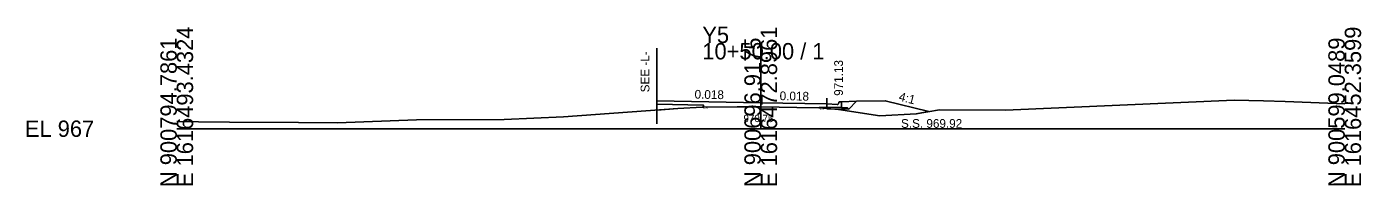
# Model space of a CAD drawing. Extents: x -26 to 1403, y -10 to 4517.
# Drawn here: x -25.7 to 202.8, y 490.3 to 517.5 of the extents above; entities that cross this region are included whole.
import ezdxf

# ---------------------------------------------------------------- set-up
doc = ezdxf.new("R2010")
doc.units = 0
for name, color, linetype in [('Exist Cross Section Cell', 7, 'Continuous'), ('Exist XS Center Line Elevation Label', 7, 'Continuous'), ('Exist XS Ground Line', 7, 'Continuous'), ('Prop XS Dump Level', 7, 'Continuous'), ('Prop XS Earthwork Shape', 7, 'Continuous'), ('Prop XS EOT Tick Mark', 7, 'Continuous'), ('Prop XS Finish Grade', 7, 'Continuous'), ('Prop XS Finish Grade CurbGutter', 7, 'Continuous'), ('Prop XS Finish Grade Earthwork', 7, 'Continuous'), ('Prop XS Finish Grade Pavement', 7, 'Continuous'), ('Prop XS Hydro Elevations', 7, 'Continuous'), ('Prop XS Pvmt Edge Slope', 7, 'Continuous'), ('Prop XS SE Text', 7, 'Continuous'), ('Prop XS Side Slope Text', 7, 'Continuous'), ('Prop XS SS Elevation Text', 7, 'Continuous'), ('Prop XS Subgrade CurbGutter', 7, 'Continuous'), ('Prop XS Subgrade Earthwork', 7, 'Continuous')]:
    doc.layers.add(name, color=color, linetype=linetype)

msp = doc.modelspace()

# ---------------------------------------------------------------- linework, layer by layer
at = {"layer": 'Exist Cross Section Cell'}
for p, q in [((100, 500), (100, 514.67)), ((0, 500), (100, 500)), ((100, 500), (200, 500))]:
    msp.add_line(p, q, dxfattribs=at)
at = {"layer": 'Exist XS Ground Line'}
for p, q in [((66.23, 502.01), (85.83, 503.47)), ((85.83, 503.47), (89.98, 503.69)), ((89.98, 503.69), (95.97, 503.75)), ((95.97, 503.75), (100.12, 503.75)), ((100.12, 503.75), (106.18, 503.64)), ((106.18, 503.64), (109.96, 503.59)), ((109.96, 503.59), (110.73, 503.53)), ((110.73, 503.53), (113.33, 503.27)), ((113.33, 503.27), (120.41, 502.22)), ((126.63, 502.53), (130.62, 503.25)), ((130.62, 503.25), (141.91, 503.15)), ((141.91, 503.15), (181.09, 504.89)), ((181.09, 504.89), (186.07, 504.77)), ((186.07, 504.77), (189.8, 504.68)), ((189.8, 504.68), (200, 504.26)), ((0, 501.21), (3.71, 501.2)), ((3.71, 501.2), (9.02, 501.11)), ((9.02, 501.11), (20.85, 501.08)), ((20.85, 501.08), (27.54, 501.02)), ((27.54, 501.02), (41.06, 501.51)), ((41.06, 501.51), (56.08, 501.6)), ((56.08, 501.6), (66.23, 502.01)), ((120.41, 502.22), (126.63, 502.53))]:
    msp.add_line(p, q, dxfattribs=at)
at = {"layer": 'Prop XS Dump Level'}
for p, q in [((82.19, 504.77), (100, 504.45)), ((100, 504.45), (111.33, 504.25))]:
    msp.add_line(p, q, dxfattribs=at)
at = {"layer": 'Prop XS Earthwork Shape'}
for points in [[(82.19, 503.2), (85.83, 503.47), (89.98, 503.69), (90.19, 503.69), (90.19, 504.04), (82.19, 504.19)], [(110.12, 503.58), (110.73, 503.53), (111.33, 503.47), (111.33, 503.66), (110.12, 503.68)], [(111.33, 503.47), (111.98, 503.4), (111.33, 503.42)], [(111.98, 503.4), (113.33, 503.27), (120.41, 502.22), (126.63, 502.53), (128.8, 502.92), (121.33, 504.79), (116.42, 504.69), (115.08, 503.35)]]:
    msp.add_lwpolyline(points, close=True, dxfattribs=at)
at = {"layer": 'Prop XS EOT Tick Mark'}
for p, q in [((82.19, 500.85), (82.19, 513.78)), ((111.33, 504.25), (111.33, 505.25))]:
    msp.add_line(p, q, dxfattribs=at)
at = {"layer": 'Prop XS Finish Grade'}
msp.add_line((113.83, 504.63), (116.42, 504.69), dxfattribs=at)
at = {"layer": 'Prop XS Finish Grade CurbGutter'}
for p, q in [((111.33, 504.25), (113.08, 504.15)), ((113.08, 504.15), (113.2, 504.17)), ((113.2, 504.17), (113.3, 504.26)), ((113.3, 504.26), (113.36, 504.51)), ((113.36, 504.51), (113.45, 504.6)), ((113.58, 504.63), (113.45, 504.6)), ((113.83, 504.63), (113.58, 504.63))]:
    msp.add_line(p, q, dxfattribs=at)
at = {"layer": 'Prop XS Finish Grade Earthwork'}
for p, q in [((116.42, 504.69), (121.33, 504.79)), ((121.33, 504.79), (128.8, 502.92))]:
    msp.add_line(p, q, dxfattribs=at)
at = {"layer": 'Prop XS Finish Grade Pavement'}
for p, q in [((82.19, 504.77), (100, 504.45)), ((100, 504.45), (111.33, 504.25))]:
    msp.add_line(p, q, dxfattribs=at)
at = {"layer": 'Prop XS Pvmt Edge Slope'}
for p, q in [((113.83, 503.62), (114.83, 503.6)), ((114.83, 503.6), (115.08, 503.35))]:
    msp.add_line(p, q, dxfattribs=at)
at = {"layer": 'Prop XS Subgrade CurbGutter'}
for p, q in [((111.33, 504.25), (111.33, 503.67)), ((111.33, 503.67), (113.83, 503.62)), ((113.83, 503.62), (113.83, 504.63))]:
    msp.add_line(p, q, dxfattribs=at)
at = {"layer": 'Prop XS Subgrade Earthwork'}
for p, q in [((82.19, 504.19), (82.19, 503.2)), ((90.19, 504.04), (82.19, 504.19)), ((90.19, 504.04), (90.19, 503.69)), ((110.12, 503.68), (110.12, 503.58)), ((110.12, 503.68), (111.33, 503.66)), ((111.33, 503.66), (111.33, 503.42)), ((111.33, 503.42), (115.08, 503.35)), ((115.08, 503.35), (116.42, 504.69))]:
    msp.add_line(p, q, dxfattribs=at)

# ---------------------------------------------------------------- texts
at = {"layer": 'Exist Cross Section Cell'}
for s, p in [('E 1616493.4324', (2.8, 490)), ('E 1616472.8961', (102.8, 490)), ('E 1616452.3599', (202.8, 490)), ('N 900794.7861', (0, 490)), ('N 900696.9175', (100, 490)), ('N 900599.0489', (200, 490))]:
    msp.add_text(s, height=2.8, rotation=90, dxfattribs=at).set_placement(p)
for s, p in [('Y5', (90, 514.67)), ('10+50.00 / 1', (90, 511.87)), ('EL 967', (-26, 498.6))]:
    msp.add_text(s, height=2.8, dxfattribs=at).set_placement(p)
at = {"layer": 'Exist XS Center Line Elevation Label'}
msp.add_text('970.75', height=1.25, dxfattribs=at).set_placement((97.05, 501.13))
at = {"layer": 'Prop XS Dump Level'}
for p in [(90.19, 503.39), (110.12, 503.28)]:
    msp.add_text('Eop', height=0.3, dxfattribs=at).set_placement(p)
at = {"layer": 'Prop XS Hydro Elevations'}
for s, p in [('SEE -L-', (80.94, 506.23)), ('971.13', (114.08, 505.63))]:
    msp.add_text(s, height=1.5, rotation=90, dxfattribs=at).set_placement(p)
at = {"layer": 'Prop XS SE Text'}
for p in [(88.66, 505.15), (103.23, 504.89)]:
    msp.add_text('0.018', height=1.5, rotation=358.9688, dxfattribs=at).set_placement(p)
at = {"layer": 'Prop XS Side Slope Text'}
msp.add_text('4:1', height=1.5, rotation=345.9638, dxfattribs=at).set_placement((123.54, 504.84))
at = {"layer": 'Prop XS SS Elevation Text'}
msp.add_text('S.S. 969.92', height=1.5, dxfattribs=at).set_placement((124.02, 500.15))

doc.saveas('drawing.dxf')
